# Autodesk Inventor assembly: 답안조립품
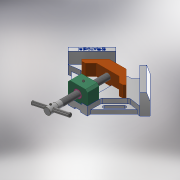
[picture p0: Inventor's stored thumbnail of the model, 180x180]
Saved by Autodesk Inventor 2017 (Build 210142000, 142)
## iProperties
Part Number: 답안조립품
Material: 일반
Document SubType Name: Assembly
Designer: 00-00
Author: 00-00
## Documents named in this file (11)
- C:\Users\00-00\Desktop\700506V1052\답안조립품.iam
- C:\Users\00-00\Desktop\700506V1052\베이스.ipt
- C:\Users\00-00\Desktop\700506V1052\리드스크류.ipt
- C:\Users\00-00\Desktop\700506V1052\핸들.ipt
- C:\Users\00-00\Desktop\700506V1052\멈춤나사 M4x5.ipt
- C:\Users\00-00\Desktop\700506V1052\서포트.ipt
- C:\Users\00-00\Desktop\700506V1052\부시.ipt
- C:\Users\00-00\Desktop\700506V1052\조.ipt
- C:\Users\00-00\Desktop\700506V1052\평행 핀 2.5x24.ipt
- C:\Users\00-00\Desktop\700506V1052\멈춤나사 M4x10.ipt
- C:\Users\00-00\Desktop\700506V1052\볼트 M4x16.ipt
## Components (1 placed, 1 different names)
1. 핸들:1
